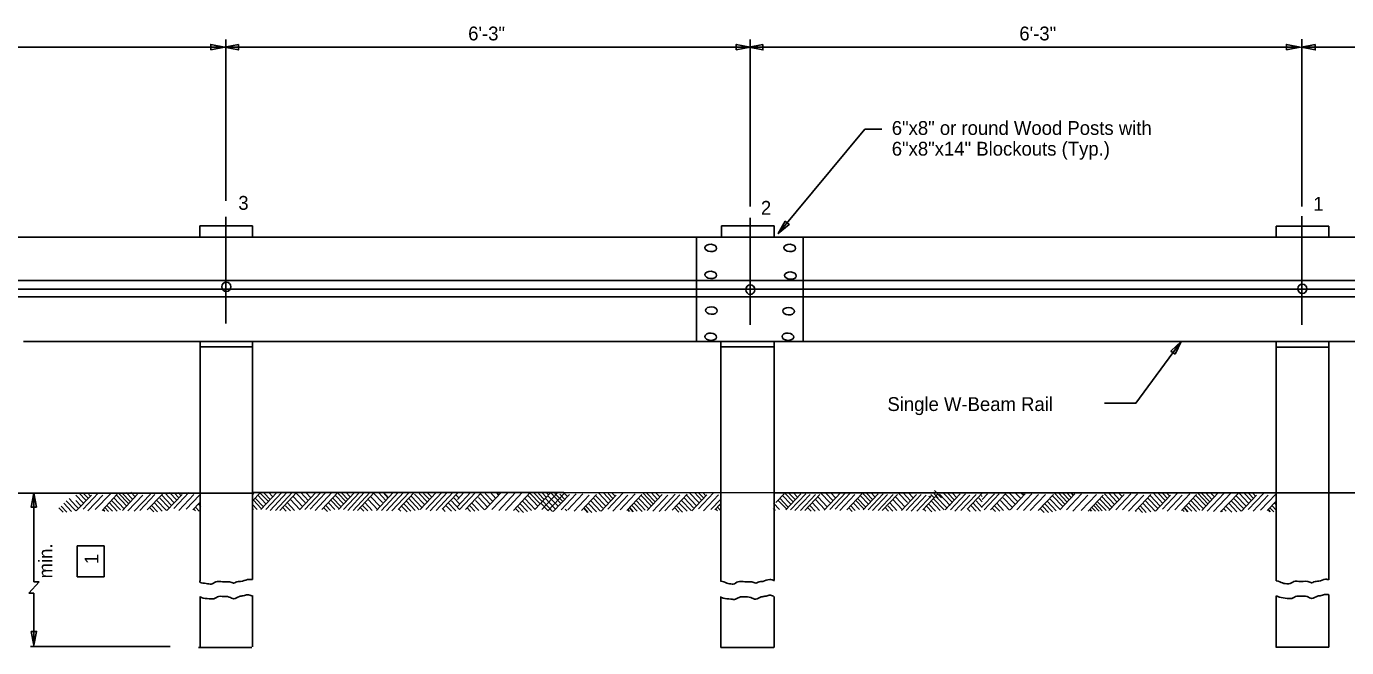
# Model space of a CAD drawing. Extents: x 0 to 34, y 0 to 22.
# Drawn here: x 8.33 to 21.69, y 8.36 to 14.65 of the extents above; entities that cross this region are included whole.
import ezdxf

# ---------------------------------------------------------------- set-up
doc = ezdxf.new("R2010")
doc.units = 0
doc.layers.add('ST_Details', color=7, linetype='Continuous')
doc.layers.add('ST_Text', color=7, linetype='Continuous')

msp = doc.modelspace()

# ---------------------------------------------------------------- linework, layer by layer
at = {"layer": 'ST_Details'}
for p, q in [((10.351, 11.641), (10.351, 12.722)), ((15.658, 11.63), (15.658, 12.713)), ((21.239, 11.63), (21.239, 12.73)), ((10.09, 12.521), (10.09, 12.631)), ((10.09, 12.631), (10.621, 12.631)), ((10.621, 12.521), (10.621, 12.631)), ((15.368, 12.52), (15.368, 12.63)), ((15.368, 12.63), (15.899, 12.63)), ((15.899, 12.52), (15.899, 12.63)), ((20.98, 12.517), (20.98, 12.626)), ((20.98, 12.626), (21.511, 12.626)), ((21.511, 12.517), (21.511, 12.626)), ((4.527, 12.517), (12.695, 12.517)), ((12.695, 12.517), (19.603, 12.517)), ((15.115, 11.46), (15.115, 12.517)), ((16.192, 11.46), (16.192, 12.517)), ((19.603, 12.517), (23.389, 12.517)), ((27.557, 12.077), (3.369, 12.077)), ((3.044, 11.99), (30.061, 11.99)), ((27.557, 11.912), (3.304, 11.912)), ((10.357, 12.014), (10.357, 12.014)), ((15.658, 11.985), (15.658, 11.985)), ((8.303, 11.46), (12.695, 11.46)), ((10.09, 11.406), (10.621, 11.406)), ((10.091, 9.931), (10.091, 11.46)), ((10.623, 9.931), (10.623, 11.46)), ((12.695, 11.46), (19.603, 11.46)), ((15.359, 9.929), (15.359, 11.466)), ((15.368, 11.405), (15.899, 11.405)), ((15.9, 9.929), (15.9, 11.459)), ((19.603, 11.46), (23.901, 11.46)), ((20.98, 9.928), (20.98, 11.46)), ((20.98, 11.402), (21.511, 11.402)), ((21.513, 9.913), (21.513, 11.456)), ((5.337, 9.925), (10.623, 9.925)), ((8.909, 9.828), (8.835, 9.906)), ((8.838, 9.746), (8.991, 9.907)), ((8.939, 9.85), (8.865, 9.929)), ((8.907, 9.765), (9.059, 9.927)), ((8.958, 9.875), (8.911, 9.924)), ((8.982, 9.896), (8.951, 9.929)), ((8.956, 9.746), (9.109, 9.907)), ((9.031, 9.759), (9.184, 9.92)), ((9.1, 9.752), (9.252, 9.914)), ((9.346, 9.797), (9.248, 9.901)), ((9.367, 9.82), (9.266, 9.926)), ((9.387, 9.838), (9.301, 9.929)), ((9.305, 9.752), (9.457, 9.914)), ((9.409, 9.864), (9.343, 9.933)), ((9.361, 9.746), (9.513, 9.907)), ((9.433, 9.89), (9.39, 9.936)), ((9.425, 9.742), (9.59, 9.916)), ((9.483, 9.749), (9.635, 9.911)), ((9.557, 9.756), (9.71, 9.917)), ((9.8, 9.803), (9.705, 9.904)), ((9.827, 9.831), (9.734, 9.93)), ((9.756, 9.749), (9.909, 9.911)), ((9.857, 9.854), (9.783, 9.932)), ((9.825, 9.769), (9.977, 9.931)), ((9.876, 9.878), (9.829, 9.928)), ((9.9, 9.9), (9.869, 9.932)), ((9.875, 9.749), (10.027, 9.911)), ((9.949, 9.763), (10.086, 9.907)), ((10.091, 9.041), (10.091, 9.934)), ((10.623, 9.052), (10.623, 9.931)), ((10.623, 9.913), (10.639, 9.931)), ((10.623, 9.847), (10.701, 9.931)), ((10.623, 9.931), (13.773, 9.931)), ((10.757, 9.817), (10.675, 9.904)), ((10.782, 9.84), (10.703, 9.924)), ((10.707, 9.759), (10.869, 9.931)), ((10.801, 9.863), (10.74, 9.927)), ((10.756, 9.759), (10.919, 9.931)), ((10.823, 9.892), (10.787, 9.931)), ((10.8, 9.752), (10.968, 9.931)), ((10.856, 9.752), (11.024, 9.931)), ((10.899, 9.752), (11.068, 9.931)), ((11.127, 9.79), (11.035, 9.888)), ((11.154, 9.831), (11.066, 9.924)), ((11.097, 9.756), (11.264, 9.932)), ((11.186, 9.85), (11.11, 9.931)), ((11.152, 9.762), (11.312, 9.931)), ((11.211, 9.879), (11.163, 9.931)), ((11.205, 9.765), (11.358, 9.927)), ((11.255, 9.752), (11.424, 9.931)), ((11.324, 9.759), (11.486, 9.931)), ((11.542, 9.817), (11.459, 9.904)), ((11.567, 9.84), (11.487, 9.924)), ((11.491, 9.759), (11.654, 9.931)), ((11.586, 9.863), (11.525, 9.927)), ((11.541, 9.759), (11.703, 9.931)), ((11.608, 9.892), (11.571, 9.931)), ((11.585, 9.752), (11.753, 9.931)), ((11.641, 9.752), (11.809, 9.931)), ((11.684, 9.752), (11.853, 9.931)), ((11.912, 9.79), (11.82, 9.888)), ((11.938, 9.831), (11.851, 9.924)), ((11.877, 9.752), (12.045, 9.931)), ((11.971, 9.85), (11.895, 9.931)), ((11.927, 9.752), (12.095, 9.931)), ((11.996, 9.879), (11.948, 9.931)), ((11.976, 9.746), (12.151, 9.931)), ((12.032, 9.746), (12.207, 9.931)), ((12.095, 9.759), (12.257, 9.931)), ((12.334, 9.782), (12.23, 9.891)), ((12.365, 9.808), (12.262, 9.917)), ((12.391, 9.836), (12.308, 9.924)), ((12.318, 9.759), (12.481, 9.931)), ((12.412, 9.86), (12.352, 9.924)), ((12.374, 9.759), (12.537, 9.931)), ((12.436, 9.884), (12.395, 9.927)), ((12.418, 9.746), (12.593, 9.931)), ((12.48, 9.752), (12.649, 9.931)), ((12.542, 9.765), (12.695, 9.927)), ((12.709, 9.878), (12.684, 9.904)), ((12.696, 9.863), (12.759, 9.931)), ((12.696, 9.791), (12.828, 9.931)), ((12.715, 9.759), (12.877, 9.931)), ((12.777, 9.759), (12.94, 9.931)), ((13.028, 9.816), (12.932, 9.917)), ((13.053, 9.842), (12.975, 9.924)), ((12.976, 9.759), (13.139, 9.931)), ((13.084, 9.873), (13.029, 9.931)), ((13.045, 9.759), (13.207, 9.931)), ((13.115, 9.905), (13.093, 9.929)), ((13.113, 9.752), (13.282, 9.931)), ((13.181, 9.752), (13.35, 9.931)), ((13.262, 9.752), (13.431, 9.931)), ((13.509, 9.793), (13.41, 9.898)), ((13.531, 9.817), (13.43, 9.924)), ((13.553, 9.841), (13.47, 9.929)), ((13.48, 9.759), (13.642, 9.931)), ((13.576, 9.858), (13.514, 9.924)), ((13.548, 9.759), (13.71, 9.931)), ((13.595, 9.883), (13.549, 9.931)), ((13.619, 9.904), (13.594, 9.931)), ((13.61, 9.746), (13.785, 9.931)), ((13.713, 9.793), (13.615, 9.896)), ((13.737, 9.826), (13.639, 9.93)), ((13.665, 9.739), (13.829, 9.912)), ((13.757, 9.845), (13.682, 9.924)), ((13.785, 9.859), (13.733, 9.914)), ((13.745, 9.757), (13.897, 9.919)), ((13.773, 9.931), (15.9, 9.929)), ((13.807, 9.894), (13.776, 9.927)), ((13.813, 9.757), (13.965, 9.919)), ((13.875, 9.744), (14.028, 9.905)), ((13.95, 9.751), (14.102, 9.912)), ((14.193, 9.798), (14.097, 9.899)), ((14.219, 9.826), (14.126, 9.925)), ((14.149, 9.744), (14.301, 9.905)), ((14.249, 9.849), (14.175, 9.927)), ((14.217, 9.764), (14.369, 9.925)), ((14.268, 9.873), (14.221, 9.922)), ((14.292, 9.894), (14.261, 9.927)), ((14.267, 9.744), (14.419, 9.905)), ((14.341, 9.757), (14.494, 9.919)), ((14.41, 9.751), (14.562, 9.912)), ((14.656, 9.796), (14.558, 9.899)), ((14.677, 9.818), (14.576, 9.925)), ((14.697, 9.837), (14.612, 9.927)), ((14.615, 9.751), (14.767, 9.912)), ((14.719, 9.863), (14.654, 9.932)), ((14.671, 9.744), (14.823, 9.905)), ((14.743, 9.888), (14.7, 9.934)), ((14.736, 9.74), (14.9, 9.914)), ((14.793, 9.748), (14.946, 9.909)), ((14.868, 9.755), (15.02, 9.916)), ((15.111, 9.802), (15.015, 9.903)), ((15.137, 9.83), (15.044, 9.929)), ((15.067, 9.748), (15.219, 9.909)), ((15.167, 9.852), (15.093, 9.931)), ((15.135, 9.768), (15.288, 9.929)), ((15.186, 9.877), (15.139, 9.926)), ((15.21, 9.898), (15.179, 9.931)), ((15.185, 9.748), (15.337, 9.909)), ((15.359, 9.035), (15.359, 9.929)), ((15.9, 9.929), (21.513, 9.929)), ((15.9, 9.044), (15.9, 9.929)), ((15.918, 9.83), (16.002, 9.919)), ((16.068, 9.815), (15.985, 9.903)), ((16.092, 9.838), (16.013, 9.922)), ((16.017, 9.757), (16.169, 9.919)), ((16.111, 9.861), (16.05, 9.926)), ((16.067, 9.757), (16.219, 9.919)), ((16.134, 9.89), (16.097, 9.929)), ((16.11, 9.751), (16.263, 9.912)), ((16.166, 9.751), (16.319, 9.912)), ((16.21, 9.751), (16.362, 9.912)), ((16.438, 9.789), (16.346, 9.886)), ((16.464, 9.83), (16.377, 9.922)), ((16.407, 9.754), (16.574, 9.931)), ((16.496, 9.848), (16.42, 9.929)), ((16.463, 9.76), (16.624, 9.931)), ((16.522, 9.878), (16.473, 9.929)), ((16.516, 9.764), (16.668, 9.925)), ((16.566, 9.751), (16.718, 9.912)), ((16.634, 9.757), (16.786, 9.919)), ((16.853, 9.815), (16.77, 9.903)), ((16.877, 9.838), (16.798, 9.922)), ((16.802, 9.757), (16.954, 9.919)), ((16.896, 9.861), (16.835, 9.926)), ((16.851, 9.757), (17.004, 9.919)), ((16.919, 9.89), (16.882, 9.929)), ((16.895, 9.751), (17.047, 9.912)), ((16.951, 9.751), (17.103, 9.912)), ((16.994, 9.751), (17.147, 9.912)), ((17.222, 9.789), (17.13, 9.886)), ((17.249, 9.83), (17.161, 9.922)), ((17.187, 9.751), (17.34, 9.912)), ((17.281, 9.848), (17.205, 9.929)), ((17.237, 9.751), (17.389, 9.912)), ((17.306, 9.878), (17.258, 9.929)), ((17.287, 9.744), (17.439, 9.905)), ((17.343, 9.744), (17.495, 9.905)), ((17.405, 9.757), (17.557, 9.919)), ((17.483, 9.878), (17.466, 9.896)), ((17.522, 9.875), (17.486, 9.912)), ((17.561, 9.876), (17.504, 9.936)), ((17.592, 9.88), (17.522, 9.954)), ((17.644, 9.78), (17.541, 9.89)), ((17.68, 9.802), (17.572, 9.916)), ((17.706, 9.83), (17.618, 9.922)), ((17.629, 9.757), (17.781, 9.919)), ((17.723, 9.858), (17.662, 9.922)), ((17.685, 9.757), (17.837, 9.919)), ((17.746, 9.883), (17.705, 9.926)), ((17.728, 9.744), (17.881, 9.905)), ((17.79, 9.751), (17.943, 9.912)), ((17.852, 9.764), (18.005, 9.925)), ((18.006, 9.891), (17.994, 9.903)), ((18.006, 9.862), (18.06, 9.919)), ((18.006, 9.79), (18.128, 9.919)), ((18.025, 9.757), (18.178, 9.919)), ((18.088, 9.757), (18.24, 9.919)), ((18.338, 9.814), (18.242, 9.916)), ((18.363, 9.84), (18.286, 9.922)), ((18.287, 9.757), (18.439, 9.919)), ((18.398, 9.867), (18.337, 9.932)), ((18.355, 9.757), (18.507, 9.919)), ((18.425, 9.904), (18.403, 9.927)), ((18.423, 9.751), (18.576, 9.912)), ((18.492, 9.751), (18.644, 9.912)), ((18.573, 9.751), (18.725, 9.912)), ((18.82, 9.791), (18.72, 9.897)), ((18.841, 9.816), (18.74, 9.922)), ((18.863, 9.839), (18.78, 9.927)), ((18.79, 9.757), (18.943, 9.919)), ((18.886, 9.857), (18.824, 9.922)), ((18.858, 9.757), (19.011, 9.919)), ((18.905, 9.881), (18.86, 9.929)), ((18.929, 9.902), (18.904, 9.929)), ((18.921, 9.744), (19.073, 9.905)), ((19.008, 9.751), (19.16, 9.912)), ((19.076, 9.744), (19.228, 9.905)), ((19.317, 9.783), (19.219, 9.887)), ((19.345, 9.81), (19.241, 9.92)), ((19.365, 9.84), (19.285, 9.925)), ((19.287, 9.751), (19.44, 9.912)), ((19.396, 9.859), (19.329, 9.929)), ((19.356, 9.757), (19.508, 9.919)), ((19.418, 9.894), (19.387, 9.927)), ((19.424, 9.757), (19.577, 9.919)), ((19.486, 9.744), (19.639, 9.905)), ((19.561, 9.751), (19.713, 9.912)), ((19.804, 9.798), (19.709, 9.899)), ((19.83, 9.826), (19.737, 9.925)), ((19.76, 9.744), (19.912, 9.905)), ((19.86, 9.849), (19.786, 9.927)), ((19.828, 9.764), (19.981, 9.925)), ((19.879, 9.873), (19.833, 9.922)), ((19.904, 9.894), (19.873, 9.927)), ((19.878, 9.744), (20.03, 9.905)), ((19.953, 9.757), (20.105, 9.919)), ((20.021, 9.751), (20.174, 9.912)), ((20.267, 9.796), (20.17, 9.899)), ((20.288, 9.818), (20.187, 9.925)), ((20.308, 9.837), (20.223, 9.927)), ((20.226, 9.751), (20.39, 9.925)), ((20.33, 9.863), (20.265, 9.932)), ((20.282, 9.744), (20.454, 9.926)), ((20.355, 9.888), (20.311, 9.934)), ((20.347, 9.74), (20.521, 9.925)), ((20.417, 9.736), (20.595, 9.924)), ((20.673, 9.796), (20.578, 9.897)), ((20.7, 9.824), (20.607, 9.923)), ((20.629, 9.742), (20.782, 9.904)), ((20.73, 9.847), (20.656, 9.925)), ((20.698, 9.762), (20.85, 9.923)), ((20.749, 9.871), (20.702, 9.921)), ((20.773, 9.892), (20.742, 9.925)), ((20.747, 9.742), (20.9, 9.904)), ((20.822, 9.755), (20.975, 9.917)), ((20.98, 9.039), (20.98, 9.93)), ((31.401, 9.928), (21.513, 9.929)), ((21.513, 9.05), (21.513, 9.911)), ((8.706, 9.733), (8.663, 9.778)), ((8.744, 9.733), (8.685, 9.795)), ((8.79, 9.74), (8.712, 9.823)), ((8.833, 9.747), (8.736, 9.849)), ((8.835, 9.798), (8.765, 9.872)), ((8.882, 9.8), (8.835, 9.85)), ((8.857, 9.775), (8.835, 9.798)), ((9.128, 9.742), (9.108, 9.762)), ((9.165, 9.74), (9.126, 9.781)), ((9.204, 9.743), (9.148, 9.802)), ((9.254, 9.742), (9.17, 9.83)), ((9.285, 9.756), (9.197, 9.849)), ((9.319, 9.771), (9.221, 9.875)), ((9.624, 9.736), (9.581, 9.782)), ((9.662, 9.736), (9.603, 9.799)), ((9.708, 9.744), (9.63, 9.827)), ((9.75, 9.751), (9.654, 9.853)), ((9.775, 9.779), (9.683, 9.876)), ((10.018, 9.756), (10.086, 9.828)), ((10.046, 9.746), (10.026, 9.766)), ((10.083, 9.744), (10.044, 9.785)), ((10.099, 9.791), (10.079, 9.811)), ((10.67, 9.761), (10.623, 9.811)), ((10.633, 9.759), (10.623, 9.77)), ((10.71, 9.771), (10.631, 9.855)), ((10.73, 9.79), (10.65, 9.875)), ((10.963, 9.744), (10.925, 9.784)), ((11.005, 9.746), (10.954, 9.799)), ((11.048, 9.752), (10.976, 9.828)), ((11.102, 9.761), (11.007, 9.861)), ((11.159, 9.826), (11.157, 9.828)), ((11.38, 9.741), (11.341, 9.782)), ((11.41, 9.752), (11.363, 9.802)), ((11.455, 9.761), (11.391, 9.828)), ((11.495, 9.771), (11.416, 9.855)), ((11.515, 9.79), (11.435, 9.875)), ((11.748, 9.744), (11.709, 9.784)), ((11.789, 9.746), (11.739, 9.799)), ((11.833, 9.752), (11.761, 9.828)), ((11.887, 9.761), (11.792, 9.861)), ((11.943, 9.826), (11.942, 9.828)), ((12.124, 9.744), (12.104, 9.765)), ((12.186, 9.737), (12.134, 9.792)), ((12.223, 9.744), (12.156, 9.815)), ((12.268, 9.752), (12.178, 9.848)), ((12.309, 9.758), (12.199, 9.875)), ((12.572, 9.74), (12.545, 9.769)), ((12.634, 9.743), (12.579, 9.802)), ((12.678, 9.747), (12.6, 9.828)), ((12.717, 9.761), (12.634, 9.848)), ((12.719, 9.815), (12.659, 9.878)), ((12.828, 9.741), (12.794, 9.777)), ((12.872, 9.744), (12.82, 9.799)), ((12.912, 9.751), (12.842, 9.825)), ((12.969, 9.756), (12.879, 9.852)), ((12.998, 9.784), (12.907, 9.881)), ((13.321, 9.732), (13.281, 9.774)), ((13.364, 9.73), (13.303, 9.795)), ((13.405, 9.739), (13.328, 9.821)), ((13.444, 9.749), (13.354, 9.844)), ((13.483, 9.762), (13.381, 9.87)), ((13.61, 9.749), (13.54, 9.823)), ((13.658, 9.74), (13.56, 9.844)), ((13.685, 9.768), (13.587, 9.871)), ((13.734, 9.81), (13.733, 9.81)), ((13.801, 9.747), (13.784, 9.764)), ((14.016, 9.731), (13.973, 9.777)), ((14.054, 9.731), (13.995, 9.793)), ((14.101, 9.738), (14.022, 9.822)), ((14.143, 9.745), (14.046, 9.847)), ((14.167, 9.773), (14.075, 9.871)), ((14.438, 9.74), (14.419, 9.76)), ((14.475, 9.738), (14.436, 9.779)), ((14.514, 9.742), (14.459, 9.8)), ((14.564, 9.741), (14.481, 9.829)), ((14.595, 9.755), (14.507, 9.847)), ((14.629, 9.77), (14.532, 9.873)), ((14.934, 9.735), (14.891, 9.781)), ((14.972, 9.735), (14.913, 9.797)), ((15.019, 9.742), (14.94, 9.825)), ((15.061, 9.749), (14.964, 9.851)), ((15.085, 9.777), (14.993, 9.875)), ((15.259, 9.761), (15.359, 9.866)), ((15.299, 9.757), (15.355, 9.816)), ((15.327, 9.746), (15.308, 9.766)), ((15.36, 9.748), (15.326, 9.785)), ((15.359, 9.794), (15.348, 9.806)), ((15.955, 9.761), (15.893, 9.826)), ((15.91, 9.751), (15.893, 9.77)), ((16.02, 9.77), (15.942, 9.853)), ((16.04, 9.788), (15.96, 9.873)), ((16.273, 9.742), (16.235, 9.783)), ((16.315, 9.744), (16.265, 9.797)), ((16.359, 9.751), (16.287, 9.827)), ((16.413, 9.76), (16.318, 9.86)), ((16.469, 9.825), (16.468, 9.826)), ((16.691, 9.74), (16.652, 9.781)), ((16.721, 9.75), (16.673, 9.801)), ((16.765, 9.76), (16.701, 9.827)), ((16.805, 9.77), (16.726, 9.853)), ((16.825, 9.788), (16.745, 9.873)), ((17.058, 9.742), (17.02, 9.783)), ((17.1, 9.744), (17.05, 9.797)), ((17.143, 9.751), (17.071, 9.827)), ((17.197, 9.76), (17.102, 9.86)), ((17.254, 9.825), (17.252, 9.826)), ((17.434, 9.742), (17.414, 9.764)), ((17.496, 9.736), (17.444, 9.791)), ((17.533, 9.743), (17.466, 9.814)), ((17.579, 9.751), (17.488, 9.847)), ((17.62, 9.757), (17.51, 9.873)), ((17.882, 9.739), (17.855, 9.768)), ((17.944, 9.742), (17.889, 9.801)), ((17.988, 9.745), (17.911, 9.827)), ((18.006, 9.782), (17.945, 9.847)), ((18.006, 9.838), (17.97, 9.876)), ((18.139, 9.739), (18.104, 9.776)), ((18.182, 9.743), (18.13, 9.797)), ((18.222, 9.75), (18.152, 9.824)), ((18.28, 9.754), (18.189, 9.85)), ((18.309, 9.783), (18.217, 9.88)), ((18.631, 9.73), (18.591, 9.772)), ((18.675, 9.729), (18.614, 9.793)), ((18.716, 9.737), (18.638, 9.819)), ((18.754, 9.748), (18.665, 9.843)), ((18.793, 9.761), (18.691, 9.868)), ((19.111, 9.745), (19.094, 9.763)), ((19.15, 9.742), (19.115, 9.779)), ((19.189, 9.743), (19.132, 9.803)), ((19.22, 9.748), (19.15, 9.822)), ((19.259, 9.749), (19.17, 9.843)), ((19.292, 9.763), (19.194, 9.866)), ((19.628, 9.731), (19.584, 9.777)), ((19.665, 9.731), (19.607, 9.793)), ((19.712, 9.738), (19.633, 9.822)), ((19.754, 9.745), (19.658, 9.847)), ((19.778, 9.773), (19.686, 9.871)), ((20.049, 9.74), (20.03, 9.76)), ((20.087, 9.738), (20.048, 9.779)), ((20.125, 9.742), (20.07, 9.8)), ((20.175, 9.741), (20.092, 9.829)), ((20.206, 9.755), (20.119, 9.847)), ((20.24, 9.77), (20.143, 9.873)), ((20.475, 9.742), (20.45, 9.768)), ((20.53, 9.732), (20.475, 9.791)), ((20.581, 9.736), (20.503, 9.82)), ((20.624, 9.743), (20.527, 9.845)), ((20.648, 9.771), (20.556, 9.869)), ((20.89, 9.749), (20.981, 9.845)), ((20.918, 9.738), (20.899, 9.759)), ((20.956, 9.736), (20.917, 9.777)), ((20.981, 9.755), (20.939, 9.798)), ((20.981, 9.806), (20.961, 9.827)), ((19.564, 9.74), (19.553, 9.751)), ((20.433, 9.738), (20.423, 9.749)), ((10.091, 8.369), (10.091, 8.879)), ((10.623, 8.371), (10.623, 8.889)), ((15.359, 8.364), (15.359, 8.874)), ((15.9, 8.363), (15.9, 8.881)), ((20.98, 8.367), (20.98, 8.886)), ((21.513, 8.367), (21.513, 8.897)), ((10.616, 8.364), (10.077, 8.364)), ((15.898, 8.364), (15.359, 8.364)), ((21.511, 8.367), (20.975, 8.367))]:
    msp.add_line(p, q, dxfattribs=at)
for centre, major_axis, ratio in [((15.259, 12.407), (-0.059, 0.0039), 0.623742), ((16.058, 12.407), (-0.059, 0.0039), 0.623742), ((15.259, 12.134), (-0.059, 0.0039), 0.623742), ((16.065, 12.127), (-0.059, 0.0039), 0.623742), ((10.357, 12.014), (0, 0.0478), 0.944544), ((15.658, 11.985), (0, 0.0478), 0.944544), ((21.244, 11.994), (0, 0.0478), 0.944544), ((15.265, 11.774), (-0.059, 0.0039), 0.623742), ((16.046, 11.767), (-0.059, 0.0039), 0.623742), ((15.259, 11.508), (-0.059, 0.0039), 0.623742), ((16.039, 11.508), (-0.059, 0.0039), 0.623742)]:
    msp.add_ellipse(centre, major_axis=major_axis, ratio=ratio, dxfattribs=at)
for points in [[(10.091, 9.041), (10.089, 9.032), (10.137, 9.014), (10.192, 9.006), (10.202, 9.006), (10.251, 9.029), (10.319, 9.029), (10.413, 9.021), (10.43, 9.015), (10.453, 9.025), (10.501, 9.032), (10.572, 9.051), (10.623, 9.052)], [(15.358, 9.035), (15.362, 9.035), (15.421, 9.015), (15.475, 9.006), (15.485, 9.006), (15.535, 9.03), (15.603, 9.03), (15.696, 9.022), (15.714, 9.016), (15.737, 9.026), (15.785, 9.033), (15.855, 9.052), (15.902, 9.039)], [(20.981, 9.038), (20.986, 9.038), (21.045, 9.017), (21.1, 9.009), (21.109, 9.009), (21.159, 9.032), (21.227, 9.032), (21.321, 9.025), (21.338, 9.018), (21.361, 9.028), (21.409, 9.035), (21.479, 9.054), (21.513, 9.05)], [(10.091, 8.879), (10.105, 8.869), (10.182, 8.858), (10.231, 8.858), (10.281, 8.881), (10.314, 8.881), (10.385, 8.875), (10.434, 8.858), (10.489, 8.881), (10.528, 8.887), (10.572, 8.898), (10.615, 8.887)], [(15.354, 8.875), (15.384, 8.864), (15.461, 8.853), (15.51, 8.853), (15.56, 8.876), (15.593, 8.876), (15.664, 8.87), (15.714, 8.853), (15.768, 8.876), (15.807, 8.882), (15.851, 8.893), (15.894, 8.882)], [(20.98, 8.886), (21.013, 8.873), (21.09, 8.861), (21.139, 8.861), (21.189, 8.884), (21.221, 8.884), (21.293, 8.879), (21.342, 8.861), (21.397, 8.884), (21.436, 8.89), (21.479, 8.902), (21.513, 8.897)]]:
    msp.add_spline(points, degree=3, dxfattribs=at)
at = {"layer": 'ST_Text'}
for p, q in [((10.34, 14.438), (5.063, 14.436)), ((10.34, 14.438), (12.691, 14.438)), ((10.351, 12.883), (10.351, 14.516)), ((12.691, 14.438), (15.657, 14.438)), ((15.647, 14.438), (19.599, 14.438)), ((15.658, 12.825), (15.658, 14.516)), ((19.599, 14.438), (21.224, 14.438)), ((21.235, 14.438), (23.385, 14.438)), ((21.239, 12.825), (21.239, 14.518)), ((15.942, 12.553), (16.816, 13.61)), ((16.988, 13.61), (16.816, 13.61)), ((8.409, 9.029), (8.409, 9.925)), ((9.121, 9.393), (8.846, 9.393)), ((8.846, 9.393), (8.846, 9.078)), ((9.121, 9.078), (9.121, 9.393)), ((8.462, 9.029), (8.359, 8.913)), ((8.409, 9.029), (8.462, 9.029)), ((8.846, 9.078), (9.121, 9.078)), ((8.359, 8.913), (8.409, 8.913)), ((8.409, 8.386), (8.409, 8.913)), ((8.374, 8.375), (9.789, 8.375))]:
    msp.add_line(p, q, dxfattribs=at)
for points in [[(10.2, 14.41), (10.2, 14.466), (10.34, 14.438)], [(10.48, 14.466), (10.48, 14.41), (10.34, 14.438)], [(15.517, 14.41), (15.517, 14.466), (15.657, 14.438)], [(15.787, 14.466), (15.787, 14.41), (15.647, 14.438)], [(21.084, 14.41), (21.084, 14.466), (21.224, 14.438)], [(21.375, 14.466), (21.375, 14.41), (21.235, 14.438)], [(16.01, 12.678), (16.053, 12.643), (15.942, 12.553)], [(19.959, 11.331), (19.914, 11.364), (20.02, 11.46)], [(8.437, 9.785), (8.381, 9.785), (8.409, 9.925)], [(8.381, 8.526), (8.437, 8.526), (8.409, 8.386)]]:
    msp.add_lwpolyline(points, close=True, dxfattribs=at)
msp.add_lwpolyline([(19.244, 10.837), (19.56, 10.837), (20.02, 11.46)], dxfattribs=at)

# ---------------------------------------------------------------- texts
for s, p in [('6\'-3"', (12.804, 14.507)), ('6\'-3"', (18.381, 14.507)), ('6"x8" or round Wood Posts with', (17.09, 13.551)), ('6"x8"x14" Blockouts (Typ.)', (17.09, 13.341)), ('3', (10.478, 12.793)), ('2', (15.766, 12.743)), ('1', (21.356, 12.784)), ('Single W-Beam Rail', (17.046, 10.757))]:
    msp.add_text(s, height=0.14, dxfattribs=at).set_placement(p)
for s, p in [('min.', (8.598, 9.063)), ('1', (9.063, 9.207))]:
    msp.add_text(s, height=0.14, rotation=90, dxfattribs=at).set_placement(p)

doc.saveas('drawing.dxf')
